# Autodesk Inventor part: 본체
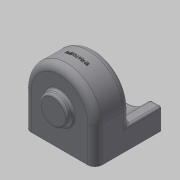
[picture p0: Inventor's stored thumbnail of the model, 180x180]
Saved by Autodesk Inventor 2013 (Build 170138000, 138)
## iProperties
Created: 2015-02
Part Number: 본체
Material: 일반
Document SubType Name: Modeling
Designer: Administrator
Density: 1 g/cm^3
Author: Administrator
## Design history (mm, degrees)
sketch "스케치1"
  geometry: L1 (-50, 0)-(-50, -50); L2 (-50, -50)-(50, -50); L3 (50, -50)-(50, 0); A1 r 50 centre (0, 0) between (50, 0) and (-50, 0); 1 further point
  constraints: 6 end point, 2 point on circle, 2 tangent, 1 centre point, 1 coincident, 1 horizontal alignment, 1 parallel, 1 perpendicular, 1 vertical
  dimensions: "d0" = 100 diameter of A1; "d2" = 50 distance from line of point (0, 0) L2
extrude "돌출1" new body sketch "스케치1" distance "d3" = 50; taper "d4" = 0 deg
feature "쉘1" dims "d5" = 4
sketch "스케치2"
  geometry: L1 (50, 0)-(50, 50) reference; L2 (50, 50)-(-50, 50) reference; L3 (-50, 50)-(-50, 0) reference; L4 (-50, 50)-(50, 50); L5 (50, 50)-(50, 20); L6 (-50, 20)-(-50, 50); L7 (50, 20)-(34.641, 20); L8 (-34.641, 20)-(-50, 20); A1 r 50 centre (0, 0) between (-50, 0) and (50, 0) reference; A2 r 40 centre (0, 0) between (34.641, 20) and (-34.641, 20)
  constraints: 10 end point, 3 collinear, 3 parallel, 2 point on circle, 1 centre point, 1 coincident, 1 horizontal, 1 perpendicular
  dimensions: "d7" = 80 diameter of A2; "d8" = 30 distance between parallel lines of L2 L8; "d9" = 30 distance between parallel lines of L2 L7
extrude "돌출2" join sketch "스케치2" distance "d10" = 45; taper "d11" = 0 deg
sketch "스케치3"
  geometry: C1 r 25 at (0, 0); A1 r 40 centre (0, 0) between (34.641, 20) and (-34.641, 20) reference
  constraints: 1 centre point, 1 coincident
  dimensions: "d12" = 50 diameter of C1
extrude "돌출3" join sketch "스케치3" distance "d15" = 10; taper "d16" = 0 deg
sketch "스케치4" dims "d17" = 36
  geometry: C1 r 25 at (0, 0) reference; C2 r 14 at (0, 0); C3 r 10 at (0, 0); 2 further points
  constraints: 3 coincident, 2 centre point, 2 vertical alignment, 2 other
  dimensions: "d18" = 28 diameter of C2; "d19" = 20 diameter of C3
extrude "돌출4" cut sketch "스케치4" distance "d20" = 10; taper "d21" = 0 deg
extrude "돌출5" cut sketch "스케치4" distance "d22" = 14; taper "d23" = 0 deg
hole "구멍1" sketch "스케치4" diameter "d24" = 2.459; stored, may be unused: countersink angle "d28" = 82 deg, drill point angle "d30" = 118 deg; dims "d25" = 6, "d26" = 3.023, "d27" = 2, "d29" = 9
fillet "모깎기1" dims "d34" = 0.3
chamfer "모따기1" distance "d35" = 1; stored, may be unused: second distance "d36" = 2, angle "d37" = 45 deg
feature "면 기울기1" dims angle "d38" = 20 deg
sketch "스케치5"
  geometry: C1 r 20 at (0, 0); A1 r 50 centre (0, 0) between (50, 0) and (-50, 0) reference
  constraints: 1 centre point, 1 coincident
  dimensions: "d39" = 40 diameter of C1
extrude "돌출6" join sketch "스케치5" distance "d42" = 9; taper "d43" = 0 deg
sketch "스케치6"
  geometry: C1 r 14 at (0, 0); C2 r 10 at (0, 0); A1 r 46 centre (0, 0) between (-46, 0) and (46, 0) reference
  constraints: 2 centre point, 2 coincident
  dimensions: "d44" = 28 diameter of C1; "d45" = 20 diameter of C2
extrude "돌출7" cut sketch "스케치6" distance "d46" = 8; taper "d47" = 0 deg
extrude "돌출8" cut sketch "스케치6" distance "d48" = 10; taper "d49" = 0 deg
fillet "모깎기2" dims "d50" = 3
fillet "모깎기3" dims "d51" = 0.3
chamfer "모따기2" distance "d52" = 1; stored, may be unused: second distance "d53" = 2, angle "d54" = 45 deg
sketch "스케치7"
  geometry: L1 (0, 0)-(100, 0) reference; L2 (0, 95)-(100, 95) reference; L3 (0, 0)-(0, 95) reference; L4 (50, 105.394)-(50, -22.188); 6 further points
  constraints: 2 end point, 1 horizontal alignment, 1 midpoint, 1 parallel, 1 point on line, 1 symmetric about line, 1 vertical alignment
  dimensions: "d55" = 9 distance from line of L2 point (8.25, 86); "d57" = 33 distance of point (8.25, 86) point (8.25, 53); "d58" = 83.5 distance of point (91.75, 86) point (8.25, 86); "d59" = 33 distance of point (91.75, 86) point (91.75, 53)
hole "구멍2" sketch "스케치7" at (8.25, 86), (91.75, 86), (91.75, 53), (8.25, 53) diameter "d60" = 5.134; stored, may be unused: countersink angle "d64" = 82 deg, drill point angle "d66" = 118 deg; dims "d61" = 10, "d62" = 3.023, "d63" = 2, "d65" = 13
fillet "모깎기4" dims "d67" = 10
fillet "모깎기5" dims "d68" = 3
fillet "모깎기6" dims "d69" = 3
fillet "모깎기7" dims "d70" = 6
node "작업 평면1"
sketch "스케치8"
  geometry: L1 (40, 0)-(-40, 0) reference; 2 further points
  constraints: 1 vertical alignment, 1 other
  dimensions: "d74" = 25 distance from line of L1 point (0, 25)
feature "엠보싱1" sketch "스케치8" dims "d0" = 100, "d2" = 50, "d7" = 80, "d8" = 30, "d9" = 30, "d72" = 0.5, "d73" = 0
node "솔리드1"
pattern_circular "원형 패턴1" dims angle "d32" = 360 deg
